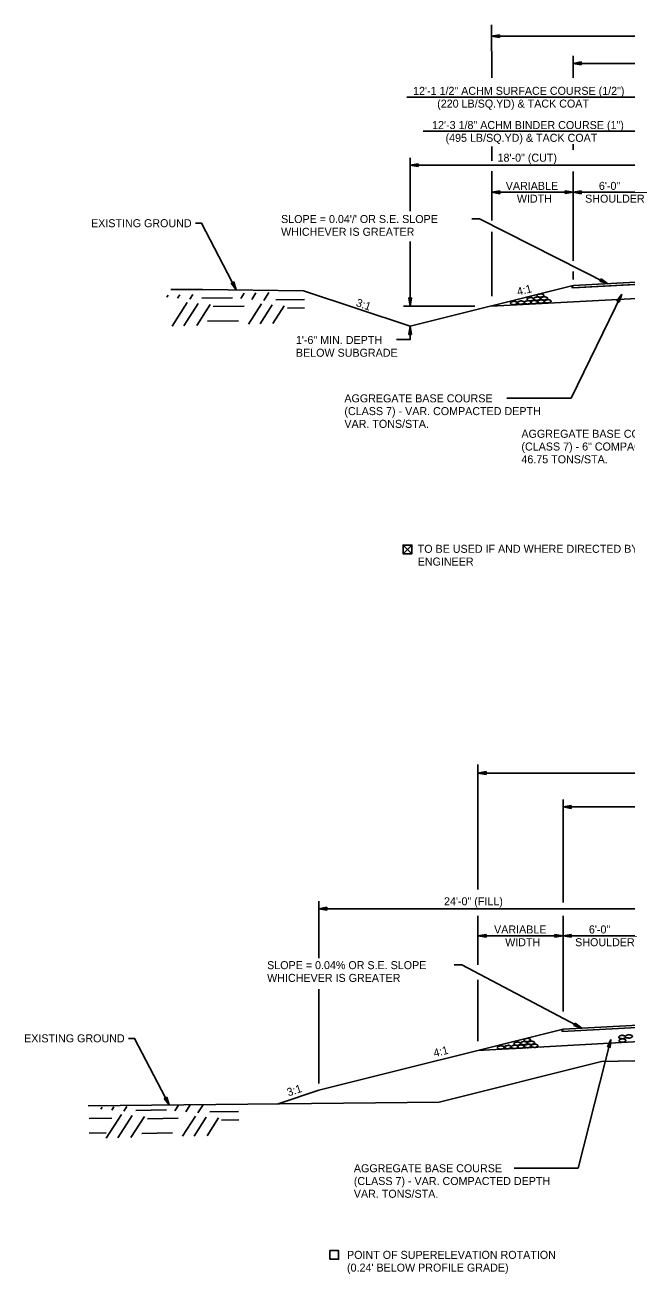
# Model space of a CAD drawing. Extents: x 1398183 to 1398373, y 1967240 to 1968889.
# Drawn here: x 1398188.4 to 1398232.6, y 1967861 to 1967953 of the extents above; entities that cross this region are included whole.
import ezdxf

# ---------------------------------------------------------------- set-up
doc = ezdxf.new("R2010")
doc.units = 0
for name, color, linetype in [('1', 7, 'Continuous'), ('10', 7, 'Continuous'), ('19', 7, 'Continuous'), ('42', 7, 'Continuous'), ('9', 7, 'Continuous'), ('Default', 7, 'Continuous'), ('Level 1', 7, 'Continuous')]:
    doc.layers.add(name, color=color, linetype=linetype)

# ---------------------------------------------------------------- blocks, each defined once
blk = doc.blocks.new('ROCKS')
at = {"layer": '1'}
blk.add_spline([(0.013, 0.06), (0.053, 0.053), (0.107, 0.033), (0.133, 0.013), (0.133, -0.007), (0.12, -0.033), (0.107, -0.04), (0.073, -0.053), (0.033, -0.067), (0.013, -0.067), (-0.02, -0.06), (-0.06, -0.053), (-0.087, -0.047), (-0.113, -0.02), (-0.113, -0.007), (-0.107, 0.02), (-0.087, 0.033), (-0.067, 0.047), (-0.033, 0.053), (-0.02, 0.06), (0.013, 0.06)], degree=3, dxfattribs=at)
blk = doc.blocks.new('4TO1 ABC')
at = {"layer": '1', "xscale": 0.1312491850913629, "yscale": 0.1312491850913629, "rotation": 180}
for p in [(0.00175, -0.00875), (-0.03325, -0.0385), (-0.016625, -0.023625), (0, -0.0385), (0.018375, -0.023625), (0.034125, -0.04025), (0.051625, -0.025375), (0.06475, -0.04025), (0.098, -0.04025), (0.133, -0.041125)]:
    blk.add_blockref('ROCKS', p, dxfattribs=at)

msp = doc.modelspace()

# ---------------------------------------------------------------- linework, layer by layer
at = {"layer": '10'}
for p, q in [((1398216.214, 1967914.676), (1398216.856, 1967914.035)), ((1398216.856, 1967914.676), (1398216.214, 1967914.035)), ((1398216.596, 1967914.035), (1398216.607, 1967914.035))]:
    msp.add_line(p, q, dxfattribs=at)
msp.add_lwpolyline([(1398216.607, 1967914.035), (1398216.856, 1967914.035), (1398216.856, 1967914.676), (1398216.214, 1967914.676), (1398216.214, 1967914.035), (1398216.596, 1967914.035)], dxfattribs=at)
msp.add_lwpolyline([(1398210.818, 1967862.037), (1398211.459, 1967862.037), (1398211.459, 1967862.679), (1398210.818, 1967862.679)], close=True, dxfattribs=at)
at = {"layer": '19'}
for p, q in [((1398223.326, 1967952.279), (1398222.726, 1967952.174)), ((1398222.726, 1967952.174), (1398223.326, 1967952.069)), ((1398222.737, 1967949.113), (1398222.727, 1967953.001)), ((1398222.727, 1967952.173), (1398286.524, 1967952.173)), ((1398223.326, 1967952.224), (1398222.886, 1967952.189)), ((1398222.886, 1967952.159), (1398223.326, 1967952.119)), ((1398223.326, 1967952.069), (1398223.326, 1967952.279)), ((1398228.734, 1967949.113), (1398228.734, 1967950.722)), ((1398229.334, 1967950.278), (1398228.734, 1967950.173)), ((1398229.334, 1967950.068), (1398229.334, 1967950.278)), ((1398278.734, 1967950.173), (1398228.734, 1967950.173)), ((1398228.734, 1967950.173), (1398229.334, 1967950.068)), ((1398229.334, 1967950.223), (1398228.894, 1967950.188)), ((1398228.894, 1967950.158), (1398229.334, 1967950.118)), ((1398216.489, 1967947.673), (1398246.731, 1967947.673)), ((1398217.678, 1967945.173), (1398270.731, 1967945.173)), ((1398222.753, 1967942.996), (1398222.754, 1967944.051)), ((1398228.73, 1967943.808), (1398228.73, 1967944.223)), ((1398216.731, 1967939.275), (1398216.731, 1967943.22)), ((1398217.331, 1967942.778), (1398216.731, 1967942.673)), ((1398234.731, 1967942.673), (1398216.731, 1967942.673)), ((1398216.731, 1967942.673), (1398217.331, 1967942.568)), ((1398217.331, 1967942.723), (1398216.891, 1967942.688)), ((1398216.891, 1967942.658), (1398217.331, 1967942.618)), ((1398217.331, 1967942.568), (1398217.331, 1967942.778)), ((1398222.737, 1967938.585), (1398222.737, 1967942.237)), ((1398228.731, 1967935.629), (1398228.731, 1967942.204)), ((1398223.337, 1967940.779), (1398222.737, 1967940.675)), ((1398222.737, 1967940.675), (1398228.743, 1967940.675)), ((1398222.737, 1967940.675), (1398223.337, 1967940.569)), ((1398223.337, 1967940.724), (1398222.897, 1967940.69)), ((1398222.897, 1967940.66), (1398223.337, 1967940.619)), ((1398223.337, 1967940.569), (1398223.337, 1967940.779)), ((1398228.144, 1967940.78), (1398228.144, 1967940.57)), ((1398228.744, 1967940.675), (1398228.144, 1967940.78)), ((1398228.584, 1967940.69), (1398228.144, 1967940.725)), ((1398228.144, 1967940.57), (1398228.744, 1967940.675)), ((1398228.144, 1967940.62), (1398228.584, 1967940.66)), ((1398229.331, 1967940.778), (1398228.731, 1967940.673)), ((1398228.731, 1967940.673), (1398234.731, 1967940.673)), ((1398228.731, 1967940.673), (1398229.331, 1967940.568)), ((1398229.331, 1967940.723), (1398228.891, 1967940.688)), ((1398228.891, 1967940.658), (1398229.331, 1967940.618)), ((1398229.331, 1967940.568), (1398229.331, 1967940.778)), ((1398221.267, 1967938.707), (1398221.837, 1967938.707)), ((1398221.837, 1967938.707), (1398231.284, 1967933.931)), ((1398222.737, 1967933.013), (1398222.737, 1967937.748)), ((1398216.731, 1967932.287), (1398216.731, 1967937.033)), ((1398228.731, 1967934.25), (1398228.731, 1967934.841)), ((1398203.548, 1967933.97), (1398203.734, 1967934.065)), ((1398203.918, 1967933.486), (1398203.548, 1967933.97)), ((1398203.836, 1967933.621), (1398203.598, 1967933.99)), ((1398203.695, 1967934.041), (1398203.857, 1967933.635)), ((1398203.734, 1967934.065), (1398203.918, 1967933.486)), ((1398228.731, 1967933.796), (1398216.731, 1967930.796)), ((1398228.731, 1967933.796), (1398228.646, 1967933.626)), ((1398230.701, 1967934.109), (1398230.797, 1967934.294)), ((1398231.284, 1967933.931), (1398230.701, 1967934.109)), ((1398231.136, 1967933.992), (1398230.728, 1967934.155)), ((1398230.775, 1967934.25), (1398231.149, 1967934.018)), ((1398230.797, 1967934.294), (1398231.284, 1967933.931)), ((1398216.731, 1967930.796), (1398208.864, 1967933.418)), ((1398216.836, 1967932.887), (1398216.626, 1967932.887)), ((1398216.626, 1967932.887), (1398216.731, 1967932.287)), ((1398216.676, 1967932.887), (1398216.716, 1967932.447)), ((1398216.731, 1967932.287), (1398216.836, 1967932.887)), ((1398216.746, 1967932.447), (1398216.781, 1967932.887)), ((1398228.589, 1967925.493), (1398232.317, 1967933.151)), ((1398232.317, 1967933.151), (1398231.953, 1967932.663)), ((1398232.235, 1967933.015), (1398232.002, 1967932.641)), ((1398232.096, 1967932.593), (1398232.26, 1967933.002)), ((1398232.14, 1967932.57), (1398232.317, 1967933.151)), ((1398221.491, 1967932.287), (1398216.242, 1967932.287)), ((1398231.953, 1967932.663), (1398232.14, 1967932.57)), ((1398216.626, 1967930.196), (1398216.731, 1967930.796)), ((1398216.836, 1967930.196), (1398216.626, 1967930.196)), ((1398216.676, 1967930.196), (1398216.716, 1967930.636)), ((1398216.731, 1967930.796), (1398216.836, 1967930.196)), ((1398216.746, 1967930.636), (1398216.781, 1967930.196)), ((1398223.861, 1967925.493), (1398228.589, 1967925.493)), ((1398221.727, 1967889.295), (1398221.727, 1967898.509)), ((1398222.327, 1967897.979), (1398221.727, 1967897.874)), ((1398221.727, 1967897.874), (1398287.019, 1967897.874)), ((1398221.727, 1967897.874), (1398222.327, 1967897.769)), ((1398222.327, 1967897.924), (1398221.887, 1967897.889)), ((1398221.887, 1967897.859), (1398222.327, 1967897.819)), ((1398222.327, 1967897.769), (1398222.327, 1967897.979)), ((1398227.996, 1967888.333), (1398227.996, 1967895.923)), ((1398228.596, 1967895.479), (1398227.996, 1967895.374)), ((1398277.997, 1967895.374), (1398227.996, 1967895.374)), ((1398227.996, 1967895.374), (1398228.596, 1967895.269)), ((1398228.596, 1967895.424), (1398228.156, 1967895.389)), ((1398228.156, 1967895.359), (1398228.596, 1967895.319)), ((1398228.596, 1967895.269), (1398228.596, 1967895.479)), ((1398209.996, 1967884.233), (1398209.996, 1967888.421)), ((1398210.596, 1967887.979), (1398209.996, 1967887.874)), ((1398233.996, 1967887.874), (1398209.996, 1967887.874)), ((1398209.996, 1967887.874), (1398210.596, 1967887.769)), ((1398210.596, 1967887.924), (1398210.156, 1967887.889)), ((1398210.156, 1967887.859), (1398210.596, 1967887.819)), ((1398210.596, 1967887.769), (1398210.596, 1967887.979)), ((1398221.726, 1967883.726), (1398221.726, 1967887.342)), ((1398227.996, 1967880.289), (1398227.996, 1967887.342)), ((1398222.326, 1967885.979), (1398221.726, 1967885.874)), ((1398221.726, 1967885.874), (1398227.996, 1967885.874)), ((1398221.726, 1967885.874), (1398222.326, 1967885.769)), ((1398222.326, 1967885.924), (1398221.886, 1967885.889)), ((1398221.886, 1967885.859), (1398222.326, 1967885.819)), ((1398222.326, 1967885.769), (1398222.326, 1967885.979)), ((1398227.396, 1967885.979), (1398227.396, 1967885.769)), ((1398227.996, 1967885.874), (1398227.396, 1967885.979)), ((1398227.836, 1967885.889), (1398227.396, 1967885.924)), ((1398227.396, 1967885.769), (1398227.996, 1967885.874)), ((1398227.396, 1967885.819), (1398227.836, 1967885.859)), ((1398228.596, 1967885.979), (1398227.996, 1967885.874)), ((1398227.996, 1967885.874), (1398233.996, 1967885.874)), ((1398227.996, 1967885.874), (1398228.596, 1967885.769)), ((1398228.596, 1967885.924), (1398228.156, 1967885.889)), ((1398228.156, 1967885.859), (1398228.596, 1967885.819)), ((1398228.596, 1967885.769), (1398228.596, 1967885.979)), ((1398219.963, 1967883.738), (1398220.533, 1967883.738)), ((1398220.533, 1967883.738), (1398229.376, 1967879.07)), ((1398221.726, 1967878.117), (1398221.726, 1967882.627)), ((1398209.996, 1967874.997), (1398209.996, 1967881.951)), ((1398228.796, 1967879.258), (1398228.895, 1967879.442)), ((1398228.872, 1967879.398), (1398229.242, 1967879.159)), ((1398228.895, 1967879.442), (1398229.376, 1967879.07)), ((1398227.996, 1967878.997), (1398209.996, 1967874.497)), ((1398227.996, 1967878.997), (1398227.911, 1967878.827)), ((1398229.376, 1967879.07), (1398228.796, 1967879.258)), ((1398229.23, 1967879.134), (1398228.824, 1967879.304)), ((1398229.117, 1967868.763), (1398231.508, 1967878.239)), ((1398231.51, 1967878.247), (1398231.266, 1967877.689)), ((1398231.266, 1967877.689), (1398231.469, 1967877.641)), ((1398231.46, 1967878.095), (1398231.318, 1967877.679)), ((1398231.421, 1967877.653), (1398231.488, 1967878.088)), ((1398231.469, 1967877.641), (1398231.51, 1967878.247)), ((1398198.618, 1967873.899), (1398198.804, 1967873.994)), ((1398198.988, 1967873.415), (1398198.618, 1967873.899)), ((1398198.906, 1967873.551), (1398198.668, 1967873.919)), ((1398198.765, 1967873.97), (1398198.927, 1967873.564)), ((1398198.804, 1967873.994), (1398198.988, 1967873.415)), ((1398209.996, 1967874.497), (1398206.997, 1967873.497)), ((1398224.388, 1967868.763), (1398229.117, 1967868.763))]:
    msp.add_line(p, q, dxfattribs=at)
for points in [[(1398200.919, 1967938.392), (1398201.365, 1967938.392), (1398203.918, 1967933.486)], [(1398278.731, 1967936.446), (1398270.731, 1967936.022), (1398258.731, 1967935.386), (1398246.731, 1967934.75), (1398234.731, 1967934.114), (1398228.731, 1967933.796)], [(1398278.813, 1967936.284), (1398270.731, 1967935.855), (1398258.731, 1967935.219), (1398246.731, 1967934.583), (1398234.731, 1967933.947), (1398228.731, 1967933.629)], [(1398246.731, 1967933.54), (1398234.372, 1967932.895), (1398222.693, 1967932.287)], [(1398227.911, 1967878.827), (1398233.911, 1967879.145), (1398270.082, 1967881.053), (1398278.081, 1967881.477)], [(1398277.996, 1967881.647), (1398269.996, 1967881.223), (1398257.996, 1967880.587), (1398245.996, 1967879.951), (1398233.996, 1967879.315), (1398227.996, 1967878.997)], [(1398270.356, 1967880.004), (1398233.636, 1967878.096), (1398221.727, 1967877.43)], [(1398195.988, 1967878.321), (1398196.434, 1967878.321), (1398198.988, 1967873.415)], [(1398230.822, 1967876.608), (1398218.869, 1967873.62), (1398193.019, 1967873.353)], [(1398246.821, 1967876.928), (1398230.822, 1967876.608)]]:
    msp.add_lwpolyline(points, dxfattribs=at)
for points in [[(1398228.646, 1967933.626), (1398234.646, 1967933.944), (1398258.722, 1967935.214), (1398270.817, 1967935.852), (1398278.813, 1967936.284), (1398278.731, 1967936.446), (1398270.731, 1967936.022), (1398258.731, 1967935.386), (1398234.731, 1967934.114), (1398228.731, 1967933.796)], [(1398227.911, 1967878.827), (1398233.911, 1967879.145), (1398255.553, 1967880.287), (1398274.081, 1967881.265), (1398278.081, 1967881.477), (1398277.996, 1967881.647), (1398273.996, 1967881.435), (1398257.996, 1967880.587), (1398233.996, 1967879.315), (1398227.996, 1967878.997)]]:
    msp.add_lwpolyline(points, close=True, dxfattribs=at)
at = {"layer": '42'}
msp.add_lwpolyline([(1398199.094, 1967933.519), (1398201.432, 1967933.519), (1398208.864, 1967933.418)], dxfattribs=at)
at = {"layer": '9'}
for p, q in [((1398198.802, 1967932.945), (1398198.902, 1967933.101)), ((1398199.601, 1967932.871), (1398199.762, 1967933.122)), ((1398200.493, 1967932.8), (1398200.714, 1967933.144)), ((1398201.382, 1967932.858), (1398203.644, 1967932.893)), ((1398204.257, 1967932.834), (1398204.514, 1967933.235)), ((1398205.056, 1967932.76), (1398205.374, 1967933.255)), ((1398205.948, 1967932.688), (1398206.326, 1967933.278)), ((1398206.837, 1967932.747), (1398208.943, 1967932.779)), ((1398199.198, 1967930.813), (1398200.314, 1967932.554)), ((1398200.058, 1967930.834), (1398201.113, 1967932.48)), ((1398201.01, 1967930.856), (1398202.005, 1967932.409)), ((1398202.231, 1967932.247), (1398204.493, 1967932.283)), ((1398204.81, 1967930.947), (1398205.769, 1967932.443)), ((1398205.67, 1967930.967), (1398206.568, 1967932.369)), ((1398206.622, 1967930.99), (1398207.46, 1967932.298)), ((1398207.686, 1967932.136), (1398208.958, 1967932.156)), ((1398201.812, 1967931.161), (1398204.073, 1967931.197)), ((1398193.949, 1967873.099), (1398194.049, 1967873.255)), ((1398194.748, 1967873.025), (1398194.909, 1967873.276)), ((1398195.64, 1967872.954), (1398195.861, 1967873.299)), ((1398196.529, 1967873.012), (1398198.791, 1967873.048)), ((1398199.404, 1967872.988), (1398199.661, 1967873.389)), ((1398200.203, 1967872.914), (1398200.521, 1967873.41)), ((1398201.095, 1967872.843), (1398201.473, 1967873.432)), ((1398201.984, 1967872.901), (1398204.09, 1967872.934)), ((1398193.081, 1967872.411), (1398194.763, 1967872.437)), ((1398194.345, 1967870.968), (1398195.461, 1967872.708)), ((1398195.205, 1967870.988), (1398196.26, 1967872.635)), ((1398196.157, 1967871.011), (1398197.152, 1967872.563)), ((1398197.378, 1967872.401), (1398199.64, 1967872.437)), ((1398199.957, 1967871.101), (1398200.916, 1967872.597)), ((1398200.817, 1967871.122), (1398201.715, 1967872.523)), ((1398201.769, 1967871.144), (1398202.607, 1967872.452)), ((1398202.833, 1967872.29), (1398204.104, 1967872.31)), ((1398193.091, 1967871.331), (1398194.343, 1967871.351)), ((1398196.959, 1967871.316), (1398199.22, 1967871.351))]:
    msp.add_line(p, q, dxfattribs=at)
at = {"layer": 'Default'}
msp.add_lwpolyline([(1398216.731, 1967930.796), (1398216.731, 1967929.816), (1398215.72, 1967929.816)], dxfattribs=at)

# ---------------------------------------------------------------- block references
at = {"layer": '19', "xscale": 14.999970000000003, "yscale": -14.999970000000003, "rotation": -178}
for p in [(1398226.331, 1967933.189), (1398225.368, 1967878.327)]:
    msp.add_blockref('4TO1 ABC', p, dxfattribs=at)
at = {"layer": 'Level 1', "xscale": 2.011654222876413, "yscale": 2.011654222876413, "rotation": 1.8263814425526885}
for p in [(1398232.337, 1967878.422), (1398232.833, 1967878.468), (1398232.351, 1967878.164)]:
    msp.add_blockref('ROCKS', p, dxfattribs=at)

# ---------------------------------------------------------------- texts
at = {"layer": '10'}
for s, height, p in [('18\'-0" (CUT)', 0.59001, (1398223.171, 1967942.925)), ('VARIABLE', 0.59, (1398223.775, 1967940.85)), ('6\'-0"', 0.59, (1398230.637, 1967940.848)), ('WIDTH', 0.59, (1398224.593, 1967939.91)), ('SHOULDER', 0.59, (1398229.624, 1967939.908)), ('EXISTING GROUND', 0.59001, (1398193.221, 1967938.097)), ('24\'-0" (FILL)', 0.59001, (1398219.227, 1967888.126)), ('VARIABLE', 0.59, (1398222.914, 1967886.049)), ('6\'-0"', 0.59, (1398229.902, 1967886.049)), ('WIDTH', 0.59, (1398223.732, 1967885.109)), ('SHOULDER', 0.59, (1398228.889, 1967885.109)), ('EXISTING GROUND', 0.59001, (1398188.29, 1967878.026)), ('POINT OF SUPERELEVATION ROTATION', 0.59001, (1398212.081, 1967862.07)), ("(0.24' BELOW PROFILE GRADE)", 0.59001, (1398212.081, 1967861.13))]:
    msp.add_text(s, height=height, dxfattribs=at).set_placement(p)
for s, height, rotation, p in [('4:1', 0.59, 14.03624, (1398224.68, 1967933.048)), ('3:1', 0.59, 340.92048, (1398212.692, 1967932.3)), ('1\'-6" MIN. DEPTH', 0.59001, 360, (1398208.314, 1967929.491)), ('BELOW SUBGRADE', 0.59001, 360, (1398208.314, 1967928.551)), ('TO BE USED IF AND WHERE DIRECTED BY THE ', 0.59001, 360, (1398217.287, 1967914.102)), ('ENGINEER', 0.59, 360, (1398217.287, 1967913.162)), ('4:1', 0.59, 14.03624, (1398218.528, 1967876.934)), ('3:1', 0.59, 18.43495, (1398207.769, 1967874.037))]:
    msp.add_text(s, height=height, rotation=rotation, dxfattribs=at).set_placement(p)
at = {"layer": '19'}
for s, p in [("SLOPE = 0.04'/' OR S.E. SLOPE", (1398207.222, 1967938.405)), ('WHICHEVER IS GREATER', (1398207.222, 1967937.465)), ('SLOPE = 0.04% OR S.E. SLOPE', (1398206.194, 1967883.42)), ('WHICHEVER IS GREATER', (1398206.194, 1967882.48))]:
    msp.add_text(s, height=0.59001, dxfattribs=at).set_placement(p)
for s, p in [('AGGREGATE BASE COURSE', (1398211.886, 1967925.19)), ('(CLASS 7) - VAR. COMPACTED DEPTH', (1398211.886, 1967924.25)), ('VAR. TONS/STA.', (1398211.886, 1967923.31)), ('AGGREGATE BASE COURSE', (1398224.929, 1967922.58)), ('(CLASS 7) - 6" COMPACTED DEPTH', (1398224.929, 1967921.64)), ('46.75 TONS/STA.', (1398224.929, 1967920.7)), ('AGGREGATE BASE COURSE', (1398212.582, 1967868.451)), ('(CLASS 7) - VAR. COMPACTED DEPTH', (1398212.582, 1967867.511)), ('VAR. TONS/STA.', (1398212.582, 1967866.571))]:
    msp.add_text(s, height=0.59001, rotation=360, dxfattribs=at).set_placement(p)
at = {"layer": '42'}
for s, p in [('12\'-1 1/2" ACHM SURFACE COURSE (1/2")', (1398216.947, 1967947.852)), ('(220 LB/SQ.YD) & TACK COAT', (1398218.724, 1967946.912)), ('12\'-3 1/8" ACHM BINDER COURSE (1")', (1398218.348, 1967945.331)), ('(495 LB/SQ.YD) & TACK COAT', (1398219.34, 1967944.391))]:
    msp.add_text(s, height=0.59001, rotation=360, dxfattribs=at).set_placement(p)

doc.saveas('drawing.dxf')
